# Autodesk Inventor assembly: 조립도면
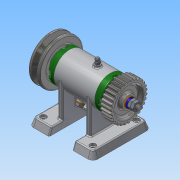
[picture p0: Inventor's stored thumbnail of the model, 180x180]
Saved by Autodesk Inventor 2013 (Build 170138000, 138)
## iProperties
Created: 2016-07
Part Number: 조립도면
Document SubType Name: Assembly
Designer: Administrator
Author: Administrator
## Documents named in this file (16)
- C:\Users\Administrator\Desktop\460708V1021\조립도면.iam
- C:\Users\Administrator\Desktop\460708V1021\V벨트풀리.ipt
- C:\Users\Administrator\Desktop\460708V1021\너트 M 8.ipt
- C:\Users\Administrator\Desktop\460708V1021\니플 M 6 x 0.75.ipt
- C:\Users\Administrator\Desktop\460708V1021\베어링 15 x 32 x 9.ipt
- C:\Users\Administrator\Desktop\460708V1021\본체.ipt
- C:\Users\Administrator\Desktop\460708V1021\볼트 M 6 x 8.ipt
- C:\Users\Administrator\Desktop\460708V1021\볼트 M4 x 12.ipt
- C:\Users\Administrator\Desktop\460708V1021\스퍼기어.ipt
- C:\Users\Administrator\Desktop\460708V1021\스프링와셔 8.ipt
- C:\Users\Administrator\Desktop\460708V1021\오일 실 15 25 7.ipt
- C:\Users\Administrator\Desktop\460708V1021\와셔 6x11.5.ipt
- C:\Users\Administrator\Desktop\460708V1021\와셔 8x17.ipt
- C:\Users\Administrator\Desktop\460708V1021\축.ipt
- C:\Users\Administrator\Desktop\460708V1021\커버.ipt
- C:\Users\Administrator\Desktop\460708V1021\키 3 x 3 x 12.ipt
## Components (11 placed, 3 different names)
1. V벨트풀리:1 — 각도:2
2. KS B 2023 6002 - 15 x 32 x 9:1
3. KS B 2023 6002 - 15 x 32 x 9:2
4. ISO 4762 M4 x 12:1
5. ISO 4762 M4 x 12:2
6. ISO 4762 M4 x 12:3
7. ISO 4762 M4 x 12:4
8. ISO 4762 M4 x 12:5
9. ISO 4762 M4 x 12:6
10. ISO 4762 M4 x 12:7
11. ISO 4762 M4 x 12:8
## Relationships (1: Angle 1)
- 각도:2 [Angle]: V벨트풀리:1
